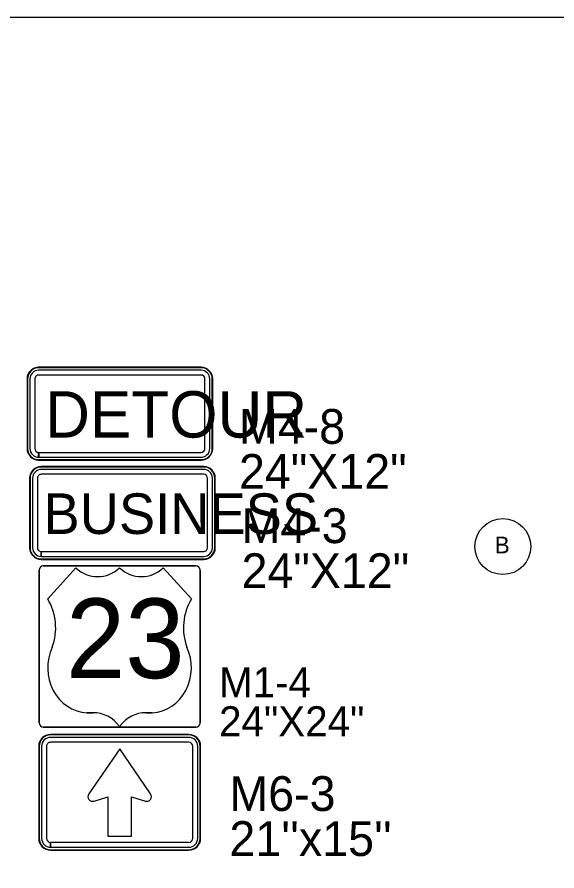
# Model space of a CAD drawing. Extents: x 886234 to 968767, y 455416 to 684046.
# Drawn here: x 957471 to 961100, y 540141 to 545883 of the extents above; entities that cross this region are included whole.
import ezdxf

# ---------------------------------------------------------------- set-up
doc = ezdxf.new("R2010")
doc.units = 0
for name, color, linetype in [('Scratch_Level_3', 7, 'Continuous'), ('TC DEV SIGN BLACK 239', 7, 'Continuous'), ('TC DEV SIGN BLACK ZERO', 7, 'Continuous'), ('TC DEV SIGN ORANGE', 7, 'Continuous'), ('TC DEV SIGN WHITE', 7, 'Continuous'), ('TC LABEL TEXT', 7, 'Continuous')]:
    doc.layers.add(name, color=color, linetype=linetype)

msp = doc.modelspace()

# ---------------------------------------------------------------- linework, layer by layer
at = {"layer": 'Scratch_Level_3'}
msp.add_lwpolyline([(933999.3, 545882.8), (968767.2, 545882.8), (968767.2, 536165.1), (933999.3, 536165.1)], close=True, dxfattribs=at)
at = {"layer": 'TC DEV SIGN BLACK 239'}
for p, q in [((958725.4, 542840.3), (957633.3, 542840.3)), ((957574.8, 542781.8), (957574.8, 542313.8)), ((957607.3, 542781.8), (957607.3, 542313.8)), ((958725.4, 542807.8), (957633.3, 542807.8)), ((958751.4, 542313.8), (958751.4, 542781.8)), ((958783.9, 542313.8), (958783.9, 542781.8)), ((957633.3, 542255.3), (957633.3, 542287.8)), ((957633.6, 542287.8), (958725.4, 542287.8)), ((957633.6, 542287.8), (957633.6, 542255.3)), ((957633.6, 542255.3), (958725.4, 542255.3)), ((958674.2, 542192.4), (957647.1, 542192.4)), ((957619.8, 542162.3), (957619.8, 541137.1)), ((957866.1, 542178.1), (957866.1, 542178.1)), ((958159.9, 542178.1), (958159.9, 542178.1)), ((958701.5, 541137.1), (958701.5, 542162.3)), ((958642.7, 541969.5), (958642.7, 541969.5)), ((957708, 541645), (957707.2, 541645)), ((958612.6, 541645), (958611.9, 541645)), ((957981.8, 541204.6), (957939.8, 541204.8)), ((958380, 541204.8), (958338.1, 541204.6)), ((957647.1, 541107), (958674.2, 541107)), ((958159.9, 541111.9), (958159.9, 541111.9)), ((958625.8, 541038.7), (957695.5, 541038.7)), ((957636.2, 540979.3), (957636.2, 540359.1)), ((957669.2, 540979.3), (957669.1, 540359.1)), ((958625.8, 541005.7), (957695.5, 541005.7)), ((958652.1, 540359.1), (958652.1, 540979.3)), ((958685.1, 540359.1), (958685.1, 540979.3)), ((957695.5, 540299.8), (957695.5, 540332.8)), ((957695.8, 540332.8), (958625.7, 540332.8)), ((957695.8, 540332.8), (957695.8, 540299.8)), ((957695.8, 540299.8), (958625.7, 540299.8))]:
    msp.add_line(p, q, dxfattribs=at)
for points in [[(957647.1, 542192.4), (958674.2, 542192.4)], [(957619.8, 541137.1), (957619.8, 542162.3)], [(957677.1, 541969.5), (957677.1, 541969.5), (957866.1, 542178.1)], [(958453.8, 542178.1), (958453.8, 542178.1), (958642.7, 541969.5)], [(958701.5, 542162.3), (958701.5, 541137.1)], [(958674.2, 541107), (957647.1, 541107)], [(958368.8, 540658.1), (958160.6, 540961.5), (957952.6, 540658.1)], [(958368.8, 540658.1), (958160.6, 540961.5), (957952.6, 540658.1)], [(958368.8, 540658.1), (958160.6, 540961.5), (957952.6, 540658.1)], [(957988.2, 540610.1), (958081.5, 540639.5), (958081.5, 540373.7), (958239.6, 540373.7)], [(957988.2, 540610.1), (958081.5, 540639.5), (958081.5, 540373.7), (958239.6, 540373.7)], [(957988.2, 540610.1), (958081.5, 540639.5), (958081.5, 540373.7), (958239.6, 540373.7)], [(958239.6, 540373.7), (958239.6, 540639.5), (958333.2, 540610.1)], [(958239.6, 540373.7), (958239.6, 540639.5), (958333.2, 540610.1)], [(958239.6, 540373.7), (958239.6, 540639.5), (958333.2, 540610.1)]]:
    msp.add_lwpolyline(points, dxfattribs=at)
for centre, start, end in [((957978.7, 540640.2), 145.55076, 287.60096), ((957978.7, 540640.2), 145.55076, 287.60096), ((957978.7, 540640.2), 145.55076, 287.60096), ((958342.6, 540640.2), 252.39904, 34.44924), ((958342.6, 540640.2), 252.39904, 34.44924), ((958342.6, 540640.2), 252.39904, 34.44924)]:
    msp.add_arc(centre, 31.6, start, end, dxfattribs=at)
for centre, major_axis, ratio, start_param, end_param in [((957633.3, 542781.8), (58.5, 0), 0.999865, 1.570796, 3.141593), ((958725.4, 542781.8), (58.5, 0), 0.999865, 0, 1.570796), ((957633.3, 542781.8), (26, 0), 0.999865, 1.570796, 3.141593), ((958725.4, 542781.8), (26, 0), 0.999865, 0, 1.570796), ((957633.3, 542313.8), (58.5, 0), 0.999865, 3.141593, 4.712389), ((957633.3, 542313.8), (26, 0), 0.999865, 3.141593, 4.712389), ((958725.4, 542313.8), (58.5, 0), 0.999865, 4.712389, 6.283185), ((958725.4, 542313.8), (26, 0), 0.999865, 4.712389, 6.283185), ((957647.1, 542162.3), (0, -30.1), 0.905624, 3.141593, 4.712389), ((957647.1, 542162.3), (0, -30.1), 0.905624, 3.141593, 4.712389), ((958674.2, 542162.3), (0, 30.1), 0.905624, 4.712389, 6.283185), ((958674.2, 542162.3), (0, 30.1), 0.905624, 4.712389, 6.283185), ((958013, 542374.8), (0, -255), 0.905624, 5.593452, 6.972919), ((958306.9, 542374.8), (0, -255), 0.905624, 5.593452, 6.972919), ((957415.6, 541775.9), (0, -347.7), 0.905624, 1.184601, 2.161129), ((958904.3, 541775.9), (0, -347.7), 0.905624, 4.122057, 5.098584), ((957950, 541505.9), (0, 301.3), 0.905624, 1.091068, 3.104197), ((958369.8, 541505.9), (0, 301.3), 0.905624, 3.178989, 5.192118), ((957981.8, 540949.7), (0, 255), 0.905624, 5.402164, 6.283185), ((958338.1, 540949.7), (0, -255), 0.905624, 3.141593, 4.022614), ((957647.1, 541137.1), (0, -30.1), 0.905624, 4.712389, 6.283185), ((957647.1, 541137.1), (0, -30.1), 0.905624, 4.712389, 6.283185), ((958674.2, 541137.1), (0, 30.1), 0.905624, 3.141593, 4.712389), ((958674.2, 541137.1), (0, 30.1), 0.905624, 3.141593, 4.712389), ((957695.5, 540979.3), (59.3, 0), 0.999865, 1.570796, 3.141593), ((958625.8, 540979.3), (59.3, 0), 0.999865, 0, 1.570796), ((957695.5, 540979.3), (26.4, 0), 0.999865, 1.570796, 3.141593), ((958625.8, 540979.3), (26.4, 0), 0.999865, 0, 1.570796), ((957695.5, 540359.1), (59.3, 0), 0.999865, 3.141593, 4.712389), ((957695.5, 540359.1), (26.4, 0), 0.999865, 3.141593, 4.712389), ((958625.7, 540359.1), (59.3, 0), 0.999865, 4.712389, 6.283185), ((958625.7, 540359.1), (26.4, 0), 0.999865, 4.712389, 6.283185)]:
    msp.add_ellipse(centre, major_axis=major_axis, ratio=ratio, start_param=start_param, end_param=end_param, dxfattribs=at)
at = {"layer": 'TC DEV SIGN BLACK ZERO'}
for p, q in [((958708.1, 543527.5), (957616, 543527.5)), ((957616, 543524.3), (957616, 543524.3)), ((958708.1, 543524.2), (957616, 543524.3)), ((958708.1, 543508), (957616, 543508)), ((958708.1, 543524.2), (958708.1, 543524.3)), ((957538, 543449.5), (957538, 542981.5)), ((957541.2, 543449.5), (957541.2, 542981.5)), ((957541.2, 543449.5), (957541.2, 543449.5)), ((957557.5, 543449.5), (957557.5, 542981.5)), ((957590, 543449.5), (957590, 542981.5)), ((958708.1, 543475.5), (957616, 543475.5)), ((958734.1, 542981.5), (958734.1, 543449.5)), ((958766.6, 542981.5), (958766.6, 543449.5)), ((958782.9, 543449.5), (958782.9, 543449.5)), ((958782.9, 542981.5), (958782.9, 543449.5)), ((958786.1, 542981.5), (958786.1, 543449.5)), ((957541.2, 542981.5), (957541.2, 542981.5)), ((957616, 542923), (957616, 542955.5)), ((957616.3, 542955.5), (958708.1, 542955.5)), ((957616.3, 542955.5), (957616.3, 542923)), ((958782.9, 542981.5), (958782.9, 542981.5)), ((957616, 542903.5), (957616, 542906.8)), ((957616, 542906.8), (957616, 542906.8)), ((957616, 542906.8), (958708.1, 542906.8)), ((957616, 542906.8), (957616, 542903.5)), ((957616, 542903.5), (958708.1, 542903.5)), ((957616.3, 542923), (958708.1, 542923)), ((958708.1, 542906.8), (958708.1, 542906.8)), ((958725.4, 542859.8), (957633.3, 542859.8)), ((957633.3, 542856.6), (957633.3, 542856.6)), ((958725.4, 542856.5), (957633.3, 542856.6)), ((958725.4, 542856.5), (958725.4, 542856.6)), ((957555.3, 542781.8), (957555.3, 542313.8)), ((957558.5, 542781.8), (957558.5, 542313.8)), ((957558.5, 542781.8), (957558.5, 542781.8)), ((958800.2, 542781.8), (958800.2, 542781.8)), ((958800.2, 542313.8), (958800.2, 542781.8)), ((958803.4, 542313.8), (958803.4, 542781.8)), ((957558.5, 542313.8), (957558.5, 542313.8)), ((958800.2, 542313.8), (958800.2, 542313.8)), ((957633.3, 542235.8), (957633.3, 542239.1)), ((957633.3, 542239.1), (957633.3, 542239.1)), ((957633.3, 542239.1), (958725.4, 542239.1)), ((957633.3, 542239.1), (957633.3, 542235.8)), ((957633.3, 542235.8), (958725.4, 542235.8)), ((958725.4, 542239.1), (958725.4, 542239.1)), ((958625.8, 541058.4), (957695.5, 541058.4)), ((957695.5, 541055.1), (957695.5, 541055.2)), ((958625.8, 541055.1), (957695.5, 541055.2)), ((958625.8, 541055.1), (958625.8, 541055.1)), ((957616.4, 540979.3), (957616.4, 540359.1)), ((957619.7, 540979.3), (957619.7, 540359.1)), ((957619.7, 540979.3), (957619.7, 540979.3)), ((958701.6, 540979.3), (958701.6, 540979.3)), ((958701.6, 540359.1), (958701.6, 540979.3)), ((958704.8, 540359.1), (958704.9, 540979.3)), ((957619.7, 540359.1), (957619.7, 540359.1)), ((958701.6, 540359.1), (958701.5, 540359.1)), ((957695.5, 540280), (957695.5, 540283.3)), ((957695.5, 540283.3), (957695.5, 540283.3)), ((957695.6, 540283.3), (958625.7, 540283.3)), ((957695.6, 540283.3), (957695.6, 540280)), ((957695.6, 540280), (958625.7, 540280)), ((958625.7, 540283.3), (958625.7, 540283.3))]:
    msp.add_line(p, q, dxfattribs=at)
for centre, major_axis, start_param, end_param in [((957616, 543449.5), (78, 0), 1.570796, 3.141593), ((957616, 543449.5), (74.8, 0), 1.570796, 3.141593), ((957616, 543449.5), (58.5, 0), 1.570796, 3.141593), ((958708.1, 543449.5), (78, 0), 0, 1.570796), ((958708.1, 543449.5), (74.8, 0), 0, 1.570796), ((958708.1, 543449.5), (58.5, 0), 0, 1.570796), ((957616, 543449.5), (26, 0), 1.570796, 3.141593), ((958708.1, 543449.5), (26, 0), 0, 1.570796), ((957616, 542981.5), (78, 0), 3.141593, 4.712389), ((957616, 542981.5), (74.8, 0), 3.141593, 4.712389), ((957616, 542981.5), (58.5, 0), 3.141593, 4.712389), ((957616, 542981.5), (26, 0), 3.141593, 4.712389), ((958708.1, 542981.5), (58.5, 0), 4.712389, 6.283185), ((958708.1, 542981.5), (26, 0), 4.712389, 6.283185), ((958708.1, 542981.5), (78, 0), 4.712389, 6.283185), ((958708.1, 542981.5), (74.8, 0), 4.712389, 6.283185), ((957633.3, 542781.8), (78, 0), 1.570796, 3.141593), ((957633.3, 542781.8), (74.8, 0), 1.570796, 3.141593), ((958725.4, 542781.8), (78, 0), 0, 1.570796), ((958725.4, 542781.8), (74.8, 0), 0, 1.570796), ((957633.3, 542313.8), (78, 0), 3.141593, 4.712389), ((957633.3, 542313.8), (74.8, 0), 3.141593, 4.712389), ((958725.4, 542313.8), (78, 0), 4.712389, 6.283185), ((958725.4, 542313.8), (74.8, 0), 4.712389, 6.283185), ((957695.5, 540979.3), (79.1, 0), 1.570796, 3.141593), ((957695.5, 540979.3), (75.8, 0), 1.570796, 3.141593), ((958625.8, 540979.3), (79.1, 0), 0, 1.570796), ((958625.8, 540979.3), (75.8, 0), 0, 1.570796), ((957695.5, 540359.1), (79.1, 0), 3.141593, 4.712389), ((957695.5, 540359.1), (75.8, 0), 3.141593, 4.712389), ((958625.7, 540359.1), (79.1, 0), 4.712389, 6.283185), ((958625.7, 540359.1), (75.8, 0), 4.712389, 6.283185)]:
    msp.add_ellipse(centre, major_axis=major_axis, ratio=0.999865, start_param=start_param, end_param=end_param, dxfattribs=at)
at = {"layer": 'TC DEV SIGN ORANGE'}
for p, q in [((958708.1, 543527.5), (957616, 543527.5)), ((957538, 543449.5), (957538, 542981.5)), ((958786.1, 542981.5), (958786.1, 543449.5)), ((957616, 542903.5), (958708.1, 542903.5))]:
    msp.add_line(p, q, dxfattribs=at)
for centre, start_param, end_param in [((957616, 543449.5), 1.570796, 3.141593), ((958708.1, 543449.5), 0, 1.570796), ((957616, 542981.5), 3.141593, 4.712389), ((958708.1, 542981.5), 4.712389, 6.283185)]:
    msp.add_ellipse(centre, major_axis=(78, 0), ratio=0.999865, start_param=start_param, end_param=end_param, dxfattribs=at)
at = {"layer": 'TC DEV SIGN WHITE'}
for p, q in [((958725.4, 542859.8), (957633.3, 542859.8)), ((957555.3, 542781.8), (957555.3, 542313.8)), ((958803.4, 542313.8), (958803.4, 542781.8)), ((957633.3, 542235.8), (958725.4, 542235.8)), ((957677.1, 541969.5), (957866.1, 542178.1)), ((957866.1, 542178.1), (957677.1, 541969.5)), ((958453.8, 542178.1), (958642.7, 541969.5)), ((958642.7, 541969.5), (958453.8, 542178.1)), ((957707.2, 541645), (957708, 541645)), ((957939.8, 541204.8), (957981.8, 541204.6)), ((958338.1, 541204.6), (958380, 541204.8)), ((958159.9, 541111.9), (958159.9, 541111.9)), ((958625.8, 541058.4), (957695.5, 541058.4)), ((957616.4, 540979.3), (957616.4, 540359.1)), ((958704.8, 540359.1), (958704.9, 540979.3)), ((957695.5, 540280), (958625.7, 540280))]:
    msp.add_line(p, q, dxfattribs=at)
for points in [[(958159.9, 542178.1), (958159.9, 542178.1)], [(958611.9, 541645), (958612.6, 541645)]]:
    msp.add_lwpolyline(points, dxfattribs=at)
for centre, major_axis, ratio, start_param, end_param in [((957633.3, 542781.8), (78, 0), 0.999865, 1.570796, 3.141593), ((958725.4, 542781.8), (78, 0), 0.999865, 0, 1.570796), ((957633.3, 542313.8), (78, 0), 0.999865, 3.141593, 4.712389), ((958725.4, 542313.8), (78, 0), 0.999865, 4.712389, 6.283185), ((958013, 542374.8), (0, -255), 0.905624, 5.593452, 6.972919), ((958013, 542374.8), (0, -255), 0.905624, 5.593452, 6.972919), ((958306.9, 542374.8), (0, -255), 0.905624, 5.593452, 6.972919), ((958306.9, 542374.8), (0, -255), 0.905624, 5.593452, 6.972919), ((957415.6, 541775.9), (0, -347.7), 0.905624, 1.184601, 2.161129), ((957415.6, 541775.9), (0, -347.7), 0.905624, 1.184601, 2.161129), ((958904.3, 541775.9), (0, -347.7), 0.905624, 4.122057, 5.098584), ((958904.3, 541775.9), (0, -347.7), 0.905624, 4.122057, 5.098584), ((957950, 541505.9), (0, 301.3), 0.905624, 1.091068, 3.104197), ((957950, 541505.9), (0, 301.3), 0.905624, 1.091068, 3.104197), ((958369.8, 541505.9), (0, 301.3), 0.905624, 3.178989, 5.192118), ((958369.8, 541505.9), (0, 301.3), 0.905624, 3.178989, 5.192118), ((957981.8, 540949.7), (0, 255), 0.905624, 5.402164, 6.283185), ((957981.8, 540949.7), (0, 255), 0.905624, 5.402164, 6.283185), ((958338.1, 540949.7), (0, -255), 0.905624, 3.141593, 4.022614), ((958338.1, 540949.7), (0, -255), 0.905624, 3.141593, 4.022614), ((957695.5, 540979.3), (79.1, 0), 0.999865, 1.570796, 3.141593), ((958625.8, 540979.3), (79.1, 0), 0.999865, 0, 1.570796), ((957695.5, 540359.1), (79.1, 0), 0.999865, 3.141593, 4.712389), ((958625.7, 540359.1), (79.1, 0), 0.999865, 4.712389, 6.283185)]:
    msp.add_ellipse(centre, major_axis=major_axis, ratio=ratio, start_param=start_param, end_param=end_param, dxfattribs=at)
at = {"layer": 'TC LABEL TEXT'}
msp.add_circle((960735.9, 542321.7), 188.1, dxfattribs=at)

# ---------------------------------------------------------------- texts
at = {"layer": 'TC DEV SIGN BLACK 239'}
for s, height, p in [('BUSINESS', 273, (957648.3, 542406.6)), ('23', 536.04, (957799.6, 541436.9))]:
    msp.add_text(s, height=height, rotation=360, dxfattribs=at).set_placement(p)
at = {"layer": 'TC DEV SIGN BLACK ZERO'}
for s, height, p in [('DETOUR', 312, (957659.3, 543054.8)), ('M4-8', 234, (958962.7, 543012.8)), ('24"X12"', 234, (958962.7, 542710.2)), ('M4-3', 234, (958980, 542345.1)), ('24"X12"', 234, (958980, 542042.5)), ('M1-4', 202.8, (958828.8, 541307.5)), ('24"X24"', 202.8, (958828.8, 541045.2)), ('M6-3', 234, (958898.2, 540543.7)), ("21''x15''", 234, (958898.2, 540241))]:
    msp.add_text(s, height=height, rotation=360, dxfattribs=at).set_placement(p)
at = {"layer": 'TC LABEL TEXT'}
msp.add_text('B', height=112.5, dxfattribs=at).set_placement((960681.8, 542276.2))

doc.saveas('drawing.dxf')
